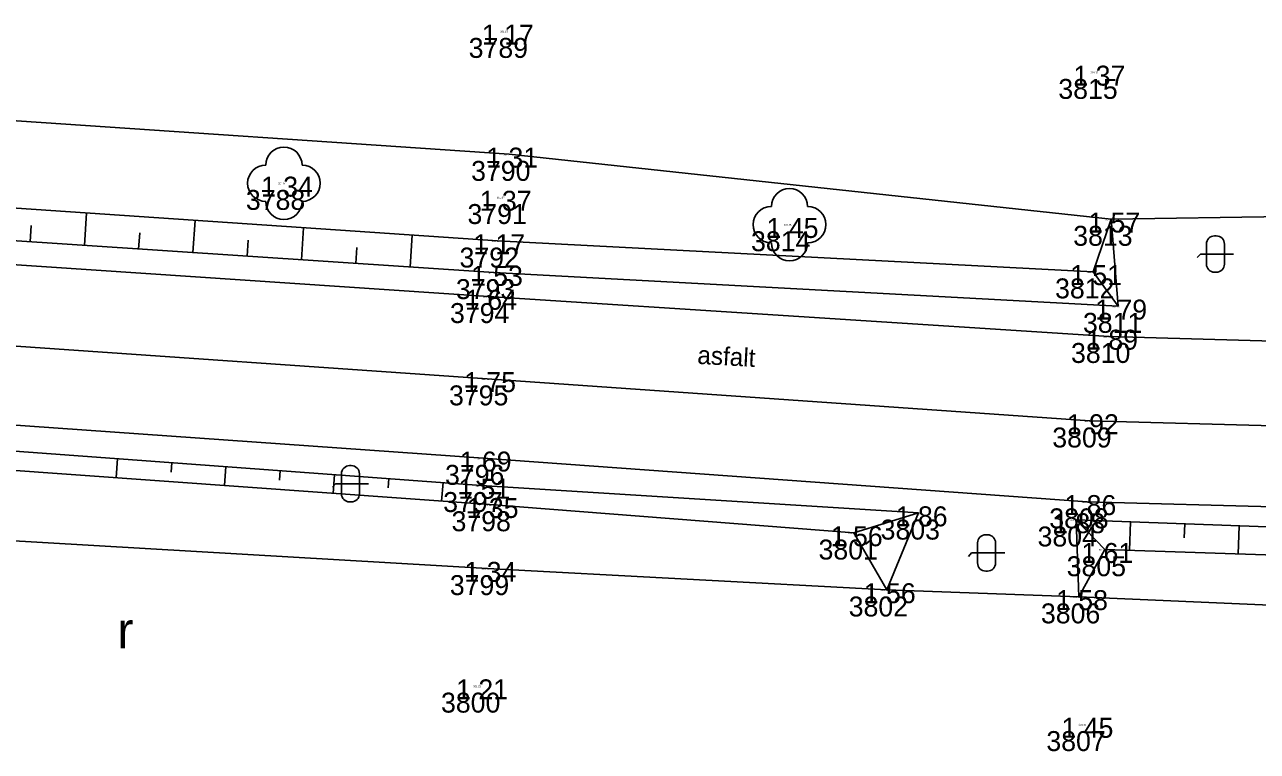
# Model space of a CAD drawing. Extents: x -740053 to -737517, y -1033516 to -1032476.
# Drawn here: x -739243.2 to -739209.21, y -1032571.5 to -1032551.47 of the extents above; entities that cross this region are included whole.
import ezdxf

# ---------------------------------------------------------------- set-up
doc = ezdxf.new("R2010")
doc.units = 0
for name, color, linetype in [('bod-cislo', 7, 'Continuous'), ('bod-oznac', 7, 'Continuous'), ('bod-vyska', 7, 'Continuous'), ('bod-vyska100', 7, 'Continuous'), ('nazvy-bud-povr', 7, 'Continuous'), ('osa-komunikace', 7, 'Continuous'), ('rozhraní kultůr', 7, 'Continuous'), ('silnice', 7, 'Continuous'), ('Technické šrafy', 7, 'Continuous'), ('Terenni-hrana', 7, 'Continuous'), ('Znacky-kultury', 7, 'Continuous')]:
    doc.layers.add(name, color=color, linetype=linetype)

# ---------------------------------------------------------------- blocks, each defined once
blk = doc.blocks.new('POINT_DISPLAY')
blk.add_line((0, 0), (0, 0))
blk = doc.blocks.new('p_strom')
for centre, start, end in [((0, 1), 0, 180), ((-1, 0), 90, 270), ((1, 0), 270, 90), ((0, -1), 180, 0)]:
    blk.add_arc(centre, 1, start, end)
at = {"rotation": -180}
blk.add_blockref('POINT_DISPLAY', (0, 0), dxfattribs=at)
blk = doc.blocks.new('p_neplod')
for p, q in [((0.052, 1.005), (-0.044, 1.005)), ((-0.824, 0.004), (-0.994, -0.184)), ((1.002, 0.004), (-0.824, 0.004)), ((-0.494, 0.555), (-0.494, -0.548)), ((0.502, -0.548), (0.502, 0.555)), ((-0.044, -0.998), (0.052, -0.998))]:
    blk.add_line(p, q)
for centre, start, end in [((-0.044, 0.555), 90, 180), ((0.052, 0.555), 0, 90), ((-0.044, -0.548), 180, 270), ((0.052, -0.548), 270, 0)]:
    blk.add_arc(centre, 0.45, start, end)
blk = doc.blocks.new('p_orna')
blk.add_text('r', height=1.996).set_placement((-0.002, 0))

msp = doc.modelspace()

# ---------------------------------------------------------------- linework, layer by layer
at = {"layer": 'osa-komunikace'}
for p, q in [((-739265.66, -1032558.8), (-739230.45, -1032561.23)), ((-739230.45, -1032561.23), (-739213.83, -1032562.39)), ((-739213.83, -1032562.39), (-739176.13, -1032563.42))]:
    msp.add_line(p, q, dxfattribs=at)
at = {"layer": 'rozhraní kultůr'}
for p, q in [((-739265.94, -1032552.58), (-739229.84, -1032555.04)), ((-739213.24, -1032556.83), (-739229.84, -1032555.04)), ((-739213.24, -1032556.83), (-739207.51, -1032556.74)), ((-739266.26, -1032564.36), (-739230.44, -1032566.46)), ((-739230.44, -1032566.46), (-739219.43, -1032567.05)), ((-739214.13, -1032567.24), (-739219.43, -1032567.05)), ((-739214.13, -1032567.24), (-739176.43, -1032568.92))]:
    msp.add_line(p, q, dxfattribs=at)
at = {"layer": 'silnice'}
for p, q in [((-739265.58, -1032556.61), (-739230.41, -1032558.96)), ((-739230.41, -1032558.96), (-739213.3, -1032560.06)), ((-739213.3, -1032560.06), (-739175.97, -1032561.16)), ((-739265.92, -1032560.92), (-739230.56, -1032563.42)), ((-739230.56, -1032563.42), (-739213.9, -1032564.62)), ((-739213.9, -1032564.62), (-739176.41, -1032565.62))]:
    msp.add_line(p, q, dxfattribs=at)
at = {"layer": 'Technické šrafy'}
for p, q in [((-739241.552, -1032557.553), (-739241.493, -1032556.659)), ((-739243.049, -1032557.454), (-739243.019, -1032557.006)), ((-739238.559, -1032557.751), (-739238.5, -1032556.863)), ((-739235.565, -1032557.949), (-739235.507, -1032557.066)), ((-739240.056, -1032557.652), (-739240.026, -1032557.207)), ((-739237.062, -1032557.85), (-739237.033, -1032557.407)), ((-739232.572, -1032558.147), (-739232.514, -1032557.27)), ((-739234.069, -1032558.048), (-739234.04, -1032557.608)), ((-739240.639, -1032563.432), (-739240.677, -1032563.957)), ((-739239.143, -1032563.542), (-739239.162, -1032563.803)), ((-739237.647, -1032563.652), (-739237.685, -1032564.173)), ((-739236.151, -1032563.762), (-739236.17, -1032564.022)), ((-739234.655, -1032563.872), (-739234.693, -1032564.389)), ((-739233.159, -1032563.982), (-739233.178, -1032564.24)), ((-739231.663, -1032564.092), (-739231.701, -1032564.605)), ((-739212.711, -1032565.174), (-739212.739, -1032565.962)), ((-739211.212, -1032565.227), (-739211.226, -1032565.619)), ((-739209.713, -1032565.281), (-739209.741, -1032566.061))]:
    msp.add_line(p, q, dxfattribs=at)
at = {"layer": 'Terenni-hrana'}
for p, q in [((-739265.74, -1032555.01), (-739230.16, -1032557.43)), ((-739265.5, -1032555.97), (-739230.26, -1032558.3)), ((-739213.74, -1032558.28), (-739213.24, -1032556.83)), ((-739213.05, -1032559.23), (-739213.24, -1032556.83)), ((-739230.16, -1032557.43), (-739213.74, -1032558.28)), ((-739230.26, -1032558.3), (-739213.05, -1032559.23)), ((-739213.05, -1032559.23), (-739213.74, -1032558.28)), ((-739266.07, -1032561.56), (-739230.61, -1032564.17)), ((-739266.14, -1032562.12), (-739230.38, -1032564.7)), ((-739230.61, -1032564.17), (-739218.55, -1032564.93)), ((-739230.38, -1032564.7), (-739220.34, -1032565.48)), ((-739218.55, -1032564.93), (-739220.34, -1032565.48)), ((-739219.43, -1032567.05), (-739218.55, -1032564.93)), ((-739214.21, -1032565.12), (-739176.43, -1032566.47)), ((-739214.21, -1032565.12), (-739213.42, -1032565.94)), ((-739214.21, -1032565.12), (-739214.13, -1032567.24)), ((-739220.34, -1032565.48), (-739219.43, -1032567.05)), ((-739214.13, -1032567.24), (-739213.42, -1032565.94)), ((-739213.42, -1032565.94), (-739176.39, -1032567.16))]:
    msp.add_line(p, q, dxfattribs=at)

# ---------------------------------------------------------------- block references
at = {"layer": 'bod-oznac'}
for p in [(-739229.92, -1032551.65), (-739213.65, -1032552.78), (-739229.84, -1032555.04), (-739236.05, -1032555.84), (-739230.02, -1032556.23), (-739222.11, -1032556.98), (-739213.24, -1032556.83), (-739230.16, -1032557.43), (-739230.26, -1032558.3), (-739213.74, -1032558.28), (-739230.41, -1032558.96), (-739213.05, -1032559.23), (-739213.3, -1032560.06), (-739230.45, -1032561.23), (-739213.83, -1032562.39), (-739230.56, -1032563.42), (-739230.61, -1032564.17), (-739230.38, -1032564.7), (-739218.55, -1032564.93), (-739213.9, -1032564.62), (-739214.21, -1032565.12), (-739220.34, -1032565.48), (-739213.42, -1032565.94), (-739230.44, -1032566.46), (-739219.43, -1032567.05), (-739214.13, -1032567.24), (-739230.67, -1032569.7), (-739213.98, -1032570.76)]:
    msp.add_blockref('POINT_DISPLAY', p, dxfattribs=at)
at = {"layer": 'Znacky-kultury', "xscale": 0.5, "yscale": 0.5}
for name, p in [('p_strom', (-739236.05, -1032555.84)), ('p_strom', (-739222.11, -1032556.98)), ('p_neplod', (-739210.369, -1032557.793)), ('p_neplod', (-739234.217, -1032564.127)), ('p_neplod', (-739216.678, -1032566.034)), ('p_orna', (-739240.639, -1032568.661))]:
    msp.add_blockref(name, p, dxfattribs=at)

# ---------------------------------------------------------------- texts
at = {"layer": 'bod-cislo'}
for s, p in [('3789', (-739230.955, -1032552.383)), ('3815', (-739214.698, -1032553.513)), ('3790', (-739230.888, -1032555.773)), ('3788', (-739237.098, -1032556.573)), ('3791', (-739230.989, -1032556.963)), ('3813', (-739214.288, -1032557.563)), ('3814', (-739223.171, -1032557.713)), ('3792', (-739231.208, -1032558.163)), ('3793', (-739231.308, -1032559.033)), ('3812', (-739214.788, -1032559.013)), ('3794', (-739231.471, -1032559.693)), ('3811', (-739214.019, -1032559.963)), ('3810', (-739214.348, -1032560.793)), ('3795', (-739231.498, -1032561.963)), ('3809', (-739214.865, -1032563.123)), ('3796', (-739231.608, -1032564.153)), ('3797', (-739231.658, -1032564.903)), ('3798', (-739231.428, -1032565.433)), ('3808', (-739214.948, -1032565.353)), ('3803', (-739219.598, -1032565.663)), ('3804', (-739215.271, -1032565.853)), ('3801', (-739221.309, -1032566.213)), ('3805', (-739214.468, -1032566.673)), ('3799', (-739231.475, -1032567.193)), ('3802', (-739220.478, -1032567.783)), ('3806', (-739215.178, -1032567.973)), ('3800', (-739231.718, -1032570.433)), ('3807', (-739215.028, -1032571.493))]:
    msp.add_text(s, height=0.55, dxfattribs=at).set_placement(p)
at = {"layer": 'bod-vyska'}
for s, p in [('1 17', (-739230.591, -1032552.017)), ('1 37', (-739214.282, -1032553.147)), ('1 31', (-739230.472, -1032555.407)), ('1 34', (-739236.682, -1032556.207)), ('1 37', (-739230.652, -1032556.597)), ('1 57', (-739213.872, -1032557.197)), ('1 45', (-739222.742, -1032557.347)), ('1 17', (-739230.831, -1032557.797)), ('1 53', (-739230.892, -1032558.667)), ('1 51', (-739214.372, -1032558.647)), ('1 64', (-739231.055, -1032559.327)), ('1 79', (-739213.682, -1032559.597)), ('1 89', (-739213.932, -1032560.427)), ('1 75', (-739231.082, -1032561.597)), ('1 92', (-739214.462, -1032562.757)), ('1 69', (-739231.205, -1032563.787)), ('1 51', (-739231.242, -1032564.537)), ('1 35', (-739231.012, -1032565.067)), ('1 86', (-739214.532, -1032564.987)), ('1 86', (-739219.182, -1032565.297)), ('1 88', (-739214.842, -1032565.487)), ('1 56', (-739220.972, -1032565.847)), ('1 61', (-739214.065, -1032566.307)), ('1 34', (-739231.072, -1032566.827)), ('1 56', (-739220.062, -1032567.417)), ('1 58', (-739214.762, -1032567.607)), ('1 21', (-739231.302, -1032570.067)), ('1 45', (-739214.612, -1032571.127))]:
    msp.add_text(s, height=0.55, dxfattribs=at).set_placement(p)
at = {"layer": 'bod-vyska100'}
for s, p in [('301 17', (-739230.083, -1032551.683)), ('301 37', (-739213.81, -1032552.813)), ('301 31', (-739230, -1032555.073)), ('301 34', (-739236.21, -1032555.873)), ('301 37', (-739230.18, -1032556.263)), ('301 45', (-739222.27, -1032557.013)), ('301 57', (-739213.4, -1032556.863)), ('301 17', (-739230.323, -1032557.463)), ('301 53', (-739230.42, -1032558.333)), ('301 51', (-739213.9, -1032558.313)), ('301 64', (-739230.571, -1032558.993)), ('301 79', (-739213.21, -1032559.263)), ('301 89', (-739213.46, -1032560.093)), ('301 75', (-739230.61, -1032561.263)), ('301 92', (-739213.99, -1032562.423)), ('301 69', (-739230.721, -1032563.453)), ('301 51', (-739230.77, -1032564.203)), ('301 35', (-739230.54, -1032564.733)), ('301 86', (-739218.71, -1032564.963)), ('301 86', (-739214.06, -1032564.653)), ('301 88', (-739214.37, -1032565.153)), ('301 56', (-739220.5, -1032565.513)), ('301 61', (-739213.581, -1032565.973)), ('301 34', (-739230.6, -1032566.493)), ('301 56', (-739219.59, -1032567.083)), ('301 58', (-739214.29, -1032567.273)), ('301 21', (-739230.83, -1032569.733)), ('301 45', (-739214.14, -1032570.793))]:
    msp.add_text(s, height=0.05, dxfattribs=at).set_placement(p)
at = {"layer": 'nazvy-bud-povr'}
msp.add_text('asfalt', height=0.5, rotation=356.8587, dxfattribs=at).set_placement((-739224.659, -1032560.817))

doc.saveas('drawing.dxf')
